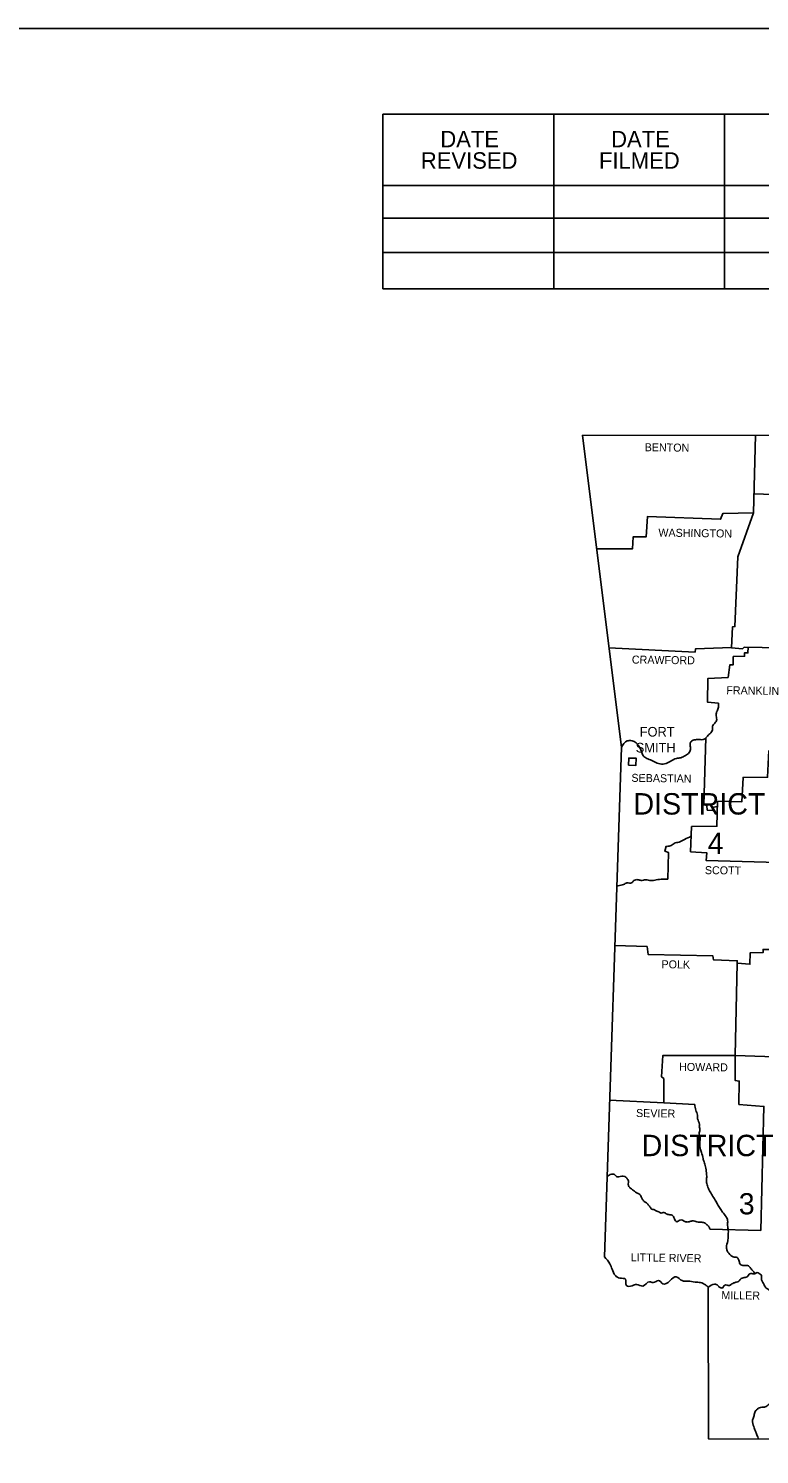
# Model space of a CAD drawing. Extents: x -819161 to 80911, y -6604 to 768454.
# Drawn here: x 80136 to 80438, y -4341 to -3752 of the extents above; entities that cross this region are included whole.
import ezdxf

# ---------------------------------------------------------------- set-up
doc = ezdxf.new("R2010")
doc.units = 0
for name, color, linetype in [('SHET_Annotations', 7, 'Continuous'), ('SHET_Border-Lines', 7, 'Continuous'), ('SHET_Border-Text', 7, 'Continuous')]:
    doc.layers.add(name, color=color, linetype=linetype)

msp = doc.modelspace()

# ---------------------------------------------------------------- linework, layer by layer
at = {"layer": 'SHET_Annotations'}
for p, q in [((80379.39, -4105.86), (80378.82, -4105.92)), ((80376.13, -4225.2), (80374.85, -4226.01))]:
    msp.add_line(p, q, dxfattribs=at)
for points in [[(80364.67, -3919.76), (80490.06, -3919.85), (80600.19, -3919.63), (80730.03, -3917.64), (80790.25, -3916.23)], [(80364.67, -3919.76), (80380.72, -4048.72), (80373.75, -4259.19)], [(80436.24, -3919.81), (80435.41, -3951.88)], [(80435.61, -3943.99), (80455.18, -3944.62), (80455.62, -3947.09), (80458.31, -3947.18), (80458.22, -3948.68), (80460.03, -3949.17), (80460.21, -3957.67), (80462.63, -3958.2), (80462.81, -3961.55), (80466.16, -3962), (80466.34, -3965.13), (80473.04, -3965.85), (80490.5, -3965.39), (80490.63, -3919.85)], [(80370.51, -3966.71), (80385.3, -3966.76), (80385.65, -3961.69), (80390.99, -3961.69), (80391.47, -3953.4), (80421.76, -3954.46), (80422.64, -3952.16), (80435.41, -3951.88), (80428.91, -3970.06), (80427.63, -3998.85), (80426.7, -3998.9), (80426.26, -4007.58), (80430.8, -4007.98), (80431.51, -4007.27), (80468.5, -4007.98), (80468.89, -4012.08)], [(80375.61, -4007.66), (80411.18, -4009.35), (80411.36, -4008.07), (80426.27, -4007.4)], [(80433.13, -4007.3), (80433.05, -4009.7), (80431.59, -4009.7), (80431.64, -4011.11), (80426.97, -4011.2), (80426.88, -4014.64), (80425.55, -4014.64), (80424.81, -4019.84), (80416.43, -4020.28), (80416.38, -4030.07), (80420.88, -4030.42)], [(80415.62, -4044.83), (80414.8, -4072.48), (80416.03, -4072.79), (80416.21, -4074.64), (80418.59, -4074.77), (80418.76, -4073.49), (80420.46, -4073.21)], [(80441.69, -4050), (80441.16, -4061.06), (80431.07, -4061.15), (80430.49, -4071.25), (80420.53, -4070.98), (80420.22, -4081.34), (80409.73, -4081.47), (80409.37, -4091.88), (80416.03, -4092.23), (80415.77, -4095.45), (80450.47, -4096.4)], [(80492.66, -4061.86), (80492.3, -4073.01), (80474.67, -4073.1), (80472.33, -4075.08), (80470.97, -4078.17), (80469.07, -4078.08), (80468.98, -4079.8), (80466.73, -4080.06), (80466.82, -4081.65), (80455.58, -4081.39), (80455.14, -4082.62), (80450.51, -4082.8), (80450.38, -4128.16), (80446.45, -4128.25), (80446.81, -4130.54), (80443.06, -4130.5), (80442.97, -4132.22), (80439.31, -4132.22), (80439.4, -4133.41), (80434.02, -4133.59), (80433.89, -4138.3), (80428.64, -4137.82), (80427.76, -4176)], [(80399.98, -4103.12), (80400.25, -4092.19), (80398.66, -4091.66), (80399.19, -4089.59)], [(80378.01, -4130.59), (80391.39, -4131.03), (80391.74, -4134.29), (80418.54, -4134.87), (80418.85, -4136.54), (80428.64, -4136.85), (80428.64, -4137.82)], [(80472.73, -4177.54), (80427.76, -4176), (80397.91, -4175.96), (80397.25, -4184.82), (80398.31, -4185.57), (80398.26, -4195.53), (80375.89, -4194.51)], [(80427.76, -4176), (80427.76, -4186.32), (80429.48, -4186.62), (80429.3, -4196.24), (80439.62, -4197.07), (80438.34, -4248.3), (80417.27, -4247.82)], [(80398.26, -4195.53), (80411.09, -4196.24)], [(80416.6, -4271.67), (80416.78, -4334.45), (80701.11, -4334.94)]]:
    msp.add_lwpolyline(points, dxfattribs=at)
msp.add_lwpolyline([(80383.67, -4056.12), (80383.76, -4053.13), (80386.85, -4053.21), (80386.76, -4056.21)], close=True, dxfattribs=at)
for points in [[(80420.88, -4030.42), (80420.88, -4032.05), (80420.26, -4033.73), (80419.87, -4035.23), (80420.13, -4037.17), (80419.43, -4038.71), (80418.41, -4039.99), (80418.41, -4041.49), (80417.27, -4043.12), (80415.99, -4044.4), (80414.93, -4045.37), (80412.95, -4045.5), (80411.31, -4045.59), (80409.73, -4046.16), (80409.11, -4047.35), (80409.37, -4049.11), (80408.76, -4050.83), (80407.17, -4052.11), (80405.36, -4052.99), (80403.51, -4053.3), (80400.91, -4054.54), (80398.62, -4055.51), (80396.1, -4055.42), (80393.81, -4054.4), (80391.69, -4053.48), (80390.06, -4052.51), (80388.78, -4049.69), (80387.9, -4048.1), (80386.4, -4046.51), (80384.68, -4045.9), (80383.19, -4046.07), (80380.72, -4048.72)], [(80399.19, -4089.59), (80400.87, -4089.45), (80402.5, -4088.4), (80404.66, -4087.87), (80406.86, -4086.76), (80409.59, -4085.46)], [(80399.98, -4103.12), (80397.78, -4103.17), (80395.18, -4103.47), (80392.84, -4103.78), (80390.77, -4103.39), (80388.87, -4103.69), (80387.55, -4103.39), (80385.92, -4103.78), (80384.95, -4104.75), (80383.01, -4104.75), (80381.64, -4105.37), (80379.39, -4105.86)], [(80411.09, -4196.24), (80411.49, -4198.57), (80412.2, -4200.64), (80412.24, -4202.14), (80412.99, -4204.48), (80412.95, -4205.32), (80413.21, -4207.08), (80412.9, -4207.96), (80413.25, -4209.82), (80413.21, -4211.27), (80413.17, -4212.42), (80413.3, -4214.36), (80413.87, -4216.08), (80414.49, -4218.59), (80414.89, -4219.96), (80415.55, -4221.98), (80415.9, -4224.45), (80415.99, -4226.26), (80415.86, -4227.98), (80416.34, -4229.92), (80417.18, -4231.86), (80418.24, -4233.71), (80419.56, -4235.83), (80420.48, -4237.5), (80421.63, -4239.27), (80422.56, -4240.72), (80424.01, -4242.62), (80424.63, -4244.16), (80424.63, -4246.28), (80424.94, -4248.35), (80424.85, -4250.55), (80424.72, -4252.62), (80424.14, -4255.36), (80424.5, -4256.68), (80426, -4258.62), (80426.92, -4259.19), (80428.55, -4259.5), (80429.3, -4260.6), (80429.79, -4262.19), (80431.42, -4262.77), (80433.23, -4262.9), (80434.11, -4263.87), (80435.25, -4265.1), (80435.96, -4266.13)], [(80376.13, -4225.2), (80377.85, -4225.16), (80378.95, -4226.17), (80379.7, -4226.08), (80380.89, -4225.91), (80382.13, -4226), (80382.92, -4226.7), (80383.63, -4227.89), (80383.58, -4229.08), (80383.63, -4229.57), (80384.2, -4230.54), (80385.13, -4231.33), (80386.14, -4232.08), (80387.02, -4232.74), (80388.61, -4233.71), (80388.78, -4234.02), (80389.36, -4235.3), (80390.15, -4236.27), (80391.08, -4236.93), (80392.09, -4237.99), (80392.53, -4238.47), (80393.33, -4239.57), (80394.16, -4239.66), (80395.4, -4240.37), (80396.24, -4240.59), (80397.12, -4241.16), (80398.04, -4240.85), (80399.23, -4241.38), (80400.78, -4241.78), (80401.66, -4242), (80402.63, -4243.45), (80403.69, -4244.69), (80404.88, -4243.98), (80407.26, -4244.69), (80408.71, -4244.73), (80410.04, -4244.34), (80411.05, -4244.47), (80412.9, -4244.91), (80414.05, -4244.91), (80415.33, -4245.35), (80416.47, -4246.28), (80417.22, -4247.33), (80417.27, -4247.82)], [(80373.75, -4259.19), (80375.96, -4262.1), (80376.88, -4264.26), (80378.25, -4266.95), (80380.14, -4268.01), (80382.39, -4268.45), (80382.83, -4271.05), (80385.17, -4271.14), (80387.07, -4270.57), (80389.62, -4271.27), (80392.36, -4269.47), (80393.9, -4269.86), (80396.1, -4268.94), (80397.87, -4270.39), (80400.82, -4269.11), (80403.42, -4267.44), (80405.89, -4269.03), (80408.32, -4269.25), (80411.18, -4269.64), (80413.43, -4269.82), (80415.46, -4270.79), (80416.6, -4271.67)], [(80416.6, -4271.67), (80419.29, -4270.52), (80420.53, -4270.88), (80421.5, -4271.89), (80422.69, -4271.94), (80423.31, -4271.01), (80424.45, -4270.88), (80425.38, -4270.97), (80426.39, -4270.39), (80427.23, -4270), (80428.38, -4269.6), (80429.26, -4269.25), (80430.01, -4268.41), (80431.46, -4267.75), (80433.05, -4267.17), (80433.49, -4266.38), (80434.28, -4266.07), (80435.83, -4266.16), (80436.89, -4265.72), (80437.72, -4266.12), (80438.47, -4266.64), (80438.65, -4268.63), (80439.27, -4269.73), (80440.24, -4271.67), (80441.51, -4272.69), (80442.75, -4273.7), (80443.19, -4274.32), (80444.56, -4275.51), (80445.7, -4275.86), (80446.23, -4276.7), (80447.07, -4278.77), (80448.35, -4280.49)], [(80448.35, -4280.49), (80447.91, -4282.78), (80447.78, -4284.59), (80448.17, -4286.62), (80447.78, -4287.68), (80448.39, -4289.13), (80449.58, -4290.28), (80450.42, -4291.51), (80450.95, -4293.36), (80450.29, -4295.35), (80451.04, -4297.42), (80451.74, -4298.21), (80452.18, -4299.49), (80451.57, -4301.83), (80450.91, -4303.63), (80449.36, -4305.4), (80448.92, -4306.28), (80449.14, -4307.43), (80449.54, -4309.28), (80449.1, -4309.85), (80448.13, -4311.17), (80447.78, -4312.63), (80447.07, -4313.91), (80446.36, -4316.11), (80445.35, -4318.01), (80445.17, -4320.12), (80443.59, -4320.08), (80441.87, -4320.12), (80440.19, -4321.23), (80438.74, -4321.31), (80436.93, -4322.06), (80435.83, -4323.52), (80435.47, -4325.15), (80434.99, -4326.69), (80435.43, -4329.34), (80436.14, -4331.19), (80436.71, -4332.69), (80437.45, -4334.49)]]:
    msp.add_spline(points, degree=3, dxfattribs=at)
at = {"layer": 'SHET_Border-Lines'}
for p, q in [((80282.17, -3859.34), (80282.17, -3787.17)), ((80352.76, -3859.34), (80352.76, -3787.17)), ((80423.34, -3859.34), (80423.34, -3787.17)), ((80282.17, -3816.54), (80564.52, -3816.54)), ((80282.17, -3830.12), (80564.52, -3830.12)), ((80282.17, -3844.29), (80564.52, -3844.29)), ((80564.52, -3859.34), (80282.17, -3859.34))]:
    msp.add_line(p, q, dxfattribs=at)
for points in [[(78502.99, -5310.09), (80911.32, -5310.09), (80911.32, -3751.75), (78502.99, -3751.75)], [(80282.17, -3859.34), (80564.52, -3859.34), (80564.52, -3880.81), (80875.91, -3880.81), (80875.91, -3787.17), (80282.17, -3787.17)]]:
    msp.add_lwpolyline(points, close=True, dxfattribs=at)

# ---------------------------------------------------------------- texts
at = {"layer": 'SHET_Annotations'}
for s, height, rotation, p in [('BENTON', 3.307, 359.2874, (80390.36, -3926.37)), ('WASHINGTON', 3.307, 359.20794, (80396.01, -3961.64)), ('CRAWFORD', 3.307, 359.27478, (80385.05, -4014.1)), ('FRANKLIN', 3.307, 359.17819, (80424.09, -4026.76)), ('SEBASTIAN', 3.307, 359.1959, (80384.87, -4062.95)), ('SCOTT', 3.307, 359.31996, (80415.24, -4101.09)), ('POLK', 3.307, 359.32331, (80397.31, -4139.97)), ('HOWARD', 3.307, 359.30301, (80404.58, -4182.34)), ('SEVIER', 3.307, 359.18154, (80386.78, -4201.43)), ('LITTLE RIVER', 3.3066, 359.20758, (80384.57, -4261.04)), ('MILLER', 3.307, 359.1885, (80422.05, -4276.65))]:
    msp.add_text(s, height=height, rotation=rotation, dxfattribs=at).set_placement(p)
for s, height, p in [('FORT', 3.968, (80388.3, -4044.26)), ('SMITH', 3.968, (80386.67, -4050.83)), ('DISTRICT', 8.845, (80385.73, -4076.48)), ('4', 8.84, (80416.39, -4092.78)), ('DISTRICT', 8.845, (80389.09, -4217.61)), ('3', 8.77, (80429.28, -4241.66))]:
    msp.add_text(s, height=height, dxfattribs=at).set_placement(p)
at = {"layer": 'SHET_Border-Text'}
for s, p in [('DATE', (80305.9, -3800.83)), ('DATE', (80376.49, -3800.83)), ('REVISED', (80297.85, -3809.67)), ('FILMED', (80371.49, -3809.67))]:
    msp.add_text(s, height=6.8, dxfattribs=at).set_placement(p)

doc.saveas('drawing.dxf')
